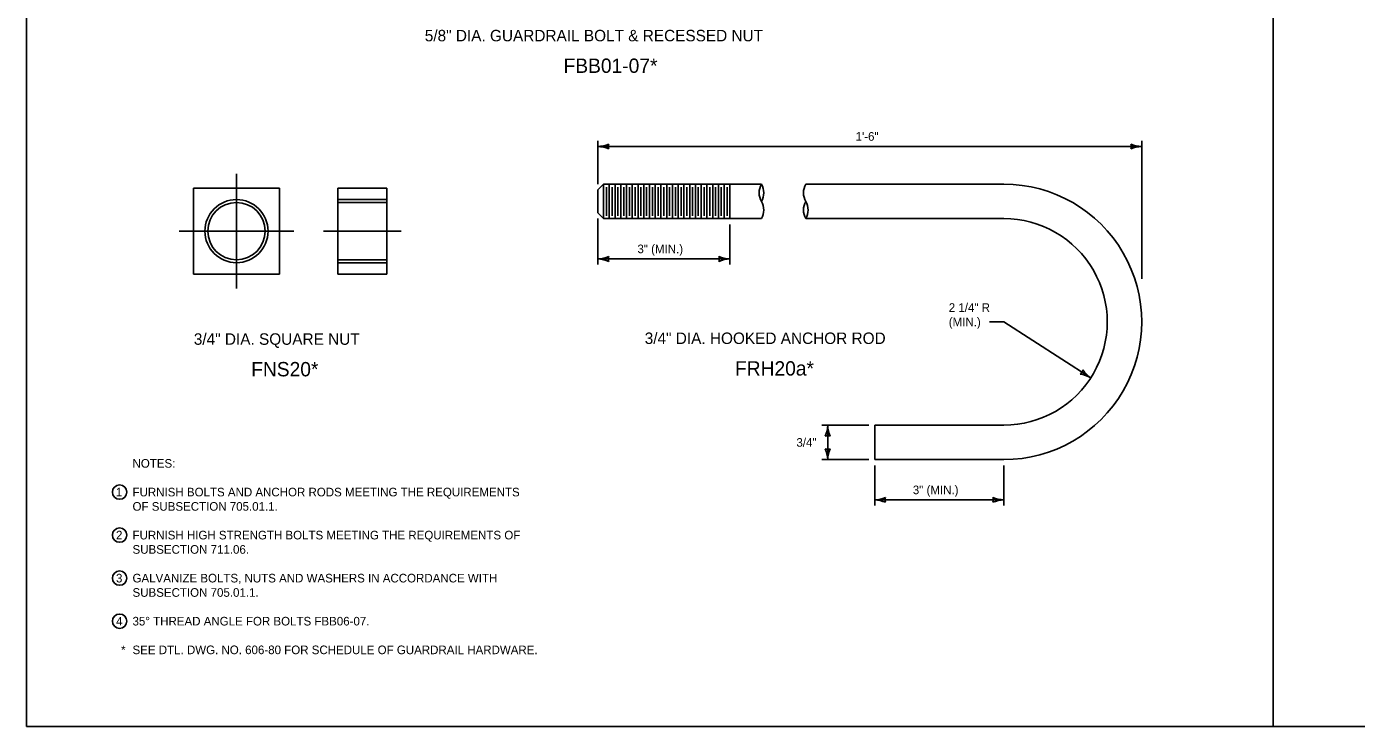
# Model space of a CAD drawing. Extents: x 49991.4 to 50021, y 49987.6 to 50011.4.
# Drawn here: x 49999.38 to 50008.65, y 49987.8 to 49992.68 of the extents above; entities that cross this region are included whole.
import ezdxf

# ---------------------------------------------------------------- set-up
doc = ezdxf.new("R2010")
doc.units = 0
for name, color, linetype in [('Level 1', 7, 'Continuous'), ('Level 2', 7, 'Continuous'), ('Level 3', 7, 'Continuous'), ('Level 4', 7, 'Continuous'), ('Level 5', 7, 'Continuous')]:
    doc.layers.add(name, color=color, linetype=linetype)

msp = doc.modelspace()

# ---------------------------------------------------------------- linework, layer by layer
at = {"layer": 'Level 1'}
for p, q in [((50008.0668, 49998.9992), (50008.0668, 49987.7988)), ((50003.3628, 49991.5385), (50003.4028, 49991.5785)), ((50004.5028, 49991.5786), (50003.4028, 49991.5785)), ((50003.4028, 49991.3385), (50003.4028, 49991.5785)), ((50003.4428, 49991.3385), (50003.4428, 49991.5785)), ((50003.4828, 49991.3385), (50003.4828, 49991.5785)), ((50003.5228, 49991.3385), (50003.5228, 49991.5785)), ((50003.5628, 49991.3385), (50003.5628, 49991.5785)), ((50003.6028, 49991.3385), (50003.6028, 49991.5785)), ((50003.6428, 49991.3385), (50003.6428, 49991.5785)), ((50003.6828, 49991.3385), (50003.6828, 49991.5785)), ((50003.7228, 49991.3385), (50003.7228, 49991.5785)), ((50003.7628, 49991.3385), (50003.7628, 49991.5785)), ((50003.8028, 49991.3385), (50003.8028, 49991.5785)), ((50003.8428, 49991.3385), (50003.8428, 49991.5785)), ((50003.8828, 49991.3385), (50003.8828, 49991.5785)), ((50003.9228, 49991.3385), (50003.9228, 49991.5785)), ((50003.9628, 49991.3385), (50003.9628, 49991.5785)), ((50004.0028, 49991.3385), (50004.0028, 49991.5785)), ((50004.0428, 49991.3386), (50004.0428, 49991.5786)), ((50004.0828, 49991.3386), (50004.0828, 49991.5786)), ((50004.1228, 49991.3386), (50004.1228, 49991.5786)), ((50004.1628, 49991.3386), (50004.1628, 49991.5786)), ((50004.2028, 49991.3386), (50004.2028, 49991.5786)), ((50004.2428, 49991.3386), (50004.2428, 49991.5786)), ((50004.2828, 49991.3386), (50004.2828, 49991.5786)), ((50006.1913, 49991.5787), (50004.8113, 49991.5786)), ((50000.5455, 49991.5517), (50001.1455, 49991.5517)), ((50000.5455, 49991.5517), (50000.5455, 49990.9517)), ((50001.1455, 49991.5517), (50001.1455, 49990.9517)), ((50001.5525, 49991.5517), (50001.5525, 49990.9517)), ((50001.5525, 49991.5517), (50001.8925, 49991.5517)), ((50001.8925, 49991.5517), (50001.8925, 49990.9517)), ((50003.3628, 49991.3785), (50003.3628, 49991.5385)), ((50003.4228, 49991.3585), (50003.4228, 49991.5585)), ((50003.4628, 49991.3585), (50003.4628, 49991.5585)), ((50003.5028, 49991.3585), (50003.5028, 49991.5585)), ((50003.5428, 49991.3585), (50003.5428, 49991.5585)), ((50003.5828, 49991.3585), (50003.5828, 49991.5585)), ((50003.6228, 49991.3585), (50003.6228, 49991.5585)), ((50003.6628, 49991.3585), (50003.6628, 49991.5585)), ((50003.7028, 49991.3585), (50003.7028, 49991.5585)), ((50003.7428, 49991.3585), (50003.7428, 49991.5585)), ((50003.7828, 49991.3585), (50003.7828, 49991.5585)), ((50003.8228, 49991.3585), (50003.8228, 49991.5585)), ((50003.8628, 49991.3585), (50003.8628, 49991.5585)), ((50003.9028, 49991.3585), (50003.9028, 49991.5585)), ((50003.9428, 49991.3585), (50003.9428, 49991.5585)), ((50003.9828, 49991.3585), (50003.9828, 49991.5585)), ((50004.0228, 49991.3585), (50004.0228, 49991.5585)), ((50004.0628, 49991.3585), (50004.0628, 49991.5585)), ((50004.1028, 49991.3585), (50004.1028, 49991.5585)), ((50004.1428, 49991.3585), (50004.1428, 49991.5585)), ((50004.1828, 49991.3585), (50004.1828, 49991.5585)), ((50004.2228, 49991.3585), (50004.2228, 49991.5585)), ((50004.2628, 49991.3585), (50004.2628, 49991.5585)), ((50003.3628, 49991.3785), (50003.4028, 49991.3385)), ((50004.5028, 49991.3386), (50003.4028, 49991.3385)), ((50006.1913, 49991.3387), (50004.8113, 49991.3386)), ((50000.5455, 49990.9517), (50001.1455, 49990.9517)), ((50001.5525, 49990.9517), (50001.8925, 49990.9517)), ((50006.1913, 49989.8987), (50005.2913, 49989.8986)), ((50005.2913, 49989.8986), (50005.2913, 49989.6586)), ((50006.1913, 49989.6587), (50005.2913, 49989.6586))]:
    msp.add_line(p, q, dxfattribs=at)
msp.add_lwpolyline([(49999.3835, 49998.9992), (50016.7501, 49998.9992), (50016.7501, 49987.7988), (49999.3835, 49987.7988)], close=True, dxfattribs=at)
msp.add_circle((50000.8455, 49991.2517), 0.2, dxfattribs=at)
for centre, radius, start, end in [((50004.6067, 49991.5186), 0.12, 149.99758, 209.9976), ((50004.3988, 49991.5186), 0.12, 329.99758, 29.9976), ((50004.9152, 49991.5186), 0.12, 149.99759, 209.99759), ((50006.1913, 49990.6187), 0.96, 269.99515, 90.00242), ((50004.3988, 49991.3986), 0.12, 330.00241, 30.00241), ((50004.9152, 49991.3986), 0.12, 150.00241, 210.00241), ((50004.7074, 49991.3986), 0.12, 330.00241, 30.00241), ((50006.1913, 49990.6187), 0.72, 269.99391, 90.00242)]:
    msp.add_arc(centre, radius, start, end, dxfattribs=at)
at = {"layer": 'Level 2'}
for centre in [(50000.0314, 49989.4325), (50000.0314, 49989.1325), (50000.0314, 49988.8325), (50000.0314, 49988.5325)]:
    msp.add_circle(centre, 0.05, dxfattribs=at)
at = {"layer": 'Level 3'}
for p, q in [((50003.3628, 49991.5785), (50003.3628, 49991.8817)), ((50007.1513, 49990.9186), (50007.1514, 49991.8817)), ((50003.3628, 49991.8417), (50007.1514, 49991.8417)), ((50003.3628, 49991.3385), (50003.3628, 49991.0178)), ((50004.2828, 49991.2986), (50004.2828, 49991.0178)), ((50004.2828, 49991.0578), (50003.3628, 49991.0578)), ((50006.1913, 49990.6187), (50006.0913, 49990.6187)), ((50006.1913, 49990.6187), (50006.7962, 49990.2281)), ((50005.2513, 49989.8986), (50004.9244, 49989.8986)), ((50004.9644, 49989.8986), (50004.9644, 49989.6586)), ((50005.2513, 49989.6586), (50004.9244, 49989.6586)), ((50005.2913, 49989.6186), (50005.2913, 49989.3379)), ((50006.1913, 49989.6187), (50006.1913, 49989.3379)), ((50005.2913, 49989.3779), (50006.1913, 49989.3779))]:
    msp.add_line(p, q, dxfattribs=at)
for centre, radius, start, end in [((50003.3536, 49992.0638), 0.2223, 272.36048, 292.54399), ((50003.491, 49991.8417), 0.0548, 162.13882, 197.86118), ((50007.0232, 49991.8417), 0.0548, 342.13882, 17.86118), ((50007.1629, 49992.0744), 0.233, 247.92284, 267.17269), ((50003.3513, 49991.609), 0.233, 67.92284, 87.17269), ((50007.1606, 49991.6195), 0.2223, 92.36048, 112.54399), ((50003.3536, 49991.2799), 0.2223, 272.36048, 292.54399), ((50003.3513, 49990.8251), 0.233, 67.92284, 87.17269), ((50003.491, 49991.0578), 0.0548, 162.13882, 197.86118), ((50004.1545, 49991.0578), 0.0548, 342.13882, 17.86118), ((50004.2942, 49991.2905), 0.233, 247.92284, 267.17269), ((50004.2919, 49990.8357), 0.2223, 92.36048, 112.54399), ((50006.6886, 49990.2979), 0.0548, 309.15424, 344.8766), ((50006.9325, 49990.4171), 0.233, 214.93826, 234.18811), ((50006.6829, 49990.0368), 0.2223, 59.3759, 79.55941), ((50004.7422, 49989.9078), 0.2223, 337.45601, 357.63952), ((50004.9644, 49989.7704), 0.0548, 72.13882, 107.86118), ((50005.1971, 49989.9101), 0.233, 182.82731, 202.07716), ((50004.9644, 49989.7868), 0.0548, 252.13882, 287.86118), ((50004.7317, 49989.6471), 0.233, 2.82731, 22.07716), ((50005.1865, 49989.6495), 0.2223, 157.45601, 177.63952), ((50005.2821, 49989.6), 0.2223, 272.36048, 292.54399), ((50005.2798, 49989.1452), 0.233, 67.92284, 87.17269), ((50005.4195, 49989.3779), 0.0548, 162.13882, 197.86118), ((50006.0631, 49989.3779), 0.0548, 342.13882, 17.86118), ((50006.2028, 49989.6106), 0.233, 247.92284, 267.17269), ((50006.2005, 49989.1558), 0.2223, 92.36048, 112.54399)]:
    msp.add_arc(centre, radius, start, end, dxfattribs=at)
at = {"layer": 'Level 4'}
for p, q in [((50001.5525, 49991.4717), (50001.8925, 49991.4717)), ((50001.5525, 49991.4517), (50001.8925, 49991.4517)), ((50001.5525, 49991.0505), (50001.8925, 49991.0505)), ((50001.5525, 49991.0317), (50001.8925, 49991.0317))]:
    msp.add_line(p, q, dxfattribs=at)
msp.add_circle((50000.8455, 49991.2517), 0.22, dxfattribs=at)
at = {"layer": 'Level 5'}
for p, q in [((50000.8455, 49990.8517), (50000.8455, 49991.6517)), ((50001.2455, 49991.2517), (50000.4455, 49991.2517)), ((50001.4525, 49991.2517), (50001.9925, 49991.2517))]:
    msp.add_line(p, q, dxfattribs=at)

# ---------------------------------------------------------------- texts
at = {"layer": 'Level 2'}
for s, height, p in [('5/8" DIA. GUARDRAIL BOLT & RECESSED NUT', 0.08, (50002.1574, 49992.5747)), ('FBB01-07*', 0.1, (50003.1242, 49992.3547)), ('1\'-6"', 0.06, (50005.1586, 49991.8817)), ('3" (MIN.)', 0.06, (50003.6386, 49991.0978)), ('2 1/4" R', 0.06, (50005.8074, 49990.6887)), ('(MIN.)', 0.06, (50005.8074, 49990.5887)), ('3/4" DIA. SQUARE NUT', 0.08, (50000.5484, 49990.4592)), ('3/4" DIA. HOOKED ANCHOR ROD', 0.08, (50003.6894, 49990.4648)), ('FNS20*', 0.1, (50000.9482, 49990.2392)), ('FRH20a*', 0.1, (50004.3185, 49990.2448)), ('3/4"', 0.06, (50004.7462, 49989.7486)), ('NOTES:', 0.06, (50000.1214, 49989.6025)), ('1', 0.06, (50000.0053, 49989.4025)), ('FURNISH BOLTS AND ANCHOR RODS MEETING THE REQUIREMENTS', 0.06, (50000.1214, 49989.4025)), ('3" (MIN.)', 0.06, (50005.5571, 49989.4179)), ('OF SUBSECTION 705.01.1.', 0.06, (50000.1214, 49989.3025)), ('2', 0.06, (50000.0062, 49989.1025)), ('FURNISH HIGH STRENGTH BOLTS MEETING THE REQUIREMENTS OF', 0.06, (50000.1214, 49989.1025)), ('SUBSECTION 711.06.', 0.06, (50000.1214, 49989.0025)), ('3', 0.06, (50000.0062, 49988.8025)), ('GALVANIZE BOLTS, NUTS AND WASHERS IN ACCORDANCE WITH ', 0.06, (50000.1214, 49988.8025)), ('SUBSECTION 705.01.1.', 0.06, (50000.1214, 49988.7025)), ('4', 0.06, (50000.0074, 49988.5025)), ('35° THREAD ANGLE FOR BOLTS FBB06-07.', 0.06, (50000.1214, 49988.5025)), ('*', 0.06, (50000.0416, 49988.3025)), ('SEE DTL. DWG. NO. 606-80 FOR SCHEDULE OF GUARDRAIL HARDWARE.', 0.06, (50000.1214, 49988.3025))]:
    msp.add_text(s, height=height, dxfattribs=at).set_placement(p)

doc.saveas('drawing.dxf')
